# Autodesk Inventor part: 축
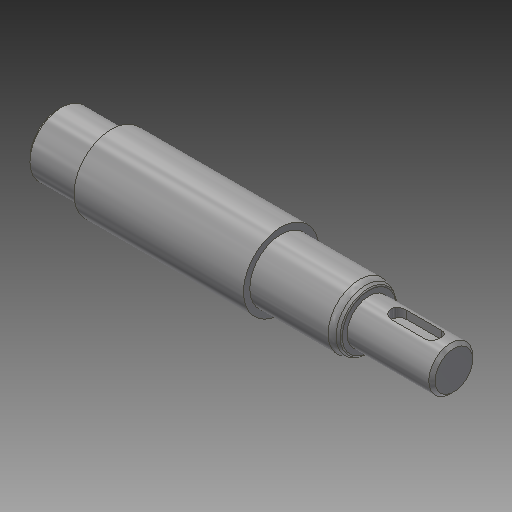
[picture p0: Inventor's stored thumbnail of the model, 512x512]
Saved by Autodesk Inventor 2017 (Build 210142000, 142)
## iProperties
Created: 2016-06
Part Number: 축
Material: 강철, 연강
Document SubType Name: Modeling
Designer: mduedu
Density: 7.86 g/cm^3
Appearance: 강철
Author: mduedu
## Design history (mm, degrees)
sketch "스케치1"
  geometry: L1 (-63, 0)-(63, 0); L2 (-63, 0)-(-63, 10); L3 (-63, 10)-(-46, 10); L4 (-46, 10)-(-46, 12); L5 (-46, 12)-(8, 12); L6 (8, 12)-(8, 10); L7 (8, 10)-(36, 10); L8 (36, 10)-(36, 7); L9 (36, 7)-(63, 7); L10 (63, 7)-(63, 0); 2 further points
  constraints: 20 end point, 5 parallel, 2 perpendicular, 1 coincident, 1 collinear, 1 horizontal, 1 midpoint, 1 vertical
  dimensions: "d0" = 126 distance of L1.start L1.end; "d2" = 14 diameter of L9 L1; "d3" = 20 diameter of L7 L1; "d4" = 24 diameter of L5 L1; "d5" = 20 diameter of L3 L1; "d6" = 17 distance of L2.end L3.end; "d7" = 27 distance of L8.end L9.end; "d8" = 55 distance from line of L5.end L10
revolve "회전1" sketch "스케치1" stored, may be unused: angle "d9" = 90 deg
sketch "스케치5"
  geometry: L1 (63, 10)-(63, -10) reference; L2 (63, -10)-(46, -10) reference; L3 (46, -10)-(46, -12) reference; L4 (46, -12)-(-8, -12) reference; L5 (-8, -12)-(-8, -10) reference; L6 (-8, -10)-(-36, -10) reference; L7 (-36, -10)-(-36, -7) reference; L8 (-36, -7)-(-63, -7) reference; L9 (-63, -7)-(-63, 7) reference; L10 (-63, 7)-(-36, 7) reference; L11 (-36, 7)-(-36, 10) reference; L12 (-36, 10)-(-8, 10) reference; L13 (-8, 10)-(-8, 12) reference; L14 (-8, 12)-(46, 12) reference; L15 (46, 12)-(46, 10) reference; L16 (46, 10)-(63, 10) reference; L17 (-63, 0)-(63, 0); L18 (-36, 8.85)-(-34.008, 10); L19 (-34.008, 10)-(-36, 10); L20 (-36, 10)-(-36, 8.85); 1 further point
  constraints: 8 end point, 2 midpoint, 2 point on line, 1 collinear, 1 perpendicular
  dimensions: "d36" = 17.7 diameter of L18.start L17; "d37" = 30 deg angle of L12 L18
revolve "회전3" sketch "스케치5" stored, may be unused: angle "d38" = 90 deg
fillet "모깎기1" dims "d13" = 4, "d39" = 0.5
node "작업 평면1"
sketch "스케치2"
  geometry: L1 (-4, 2.5)-(7, 2.5); L2 (7, -2.5)-(-4, -2.5); L3 (-4, 0)-(7, 0); L4 (-13.5, 8.561)-(-13.5, -8.561) reference; A1 r 2.5 centre (-4, 0) between (-4, 2.5) and (-4, -2.5); A2 r 2.5 centre (7, 0) between (7, -2.5) and (7, 2.5); 1 further point
  constraints: 6 end point, 4 point on circle, 3 tangent, 2 centre point, 2 parallel, 1 horizontal, 1 horizontal alignment
  dimensions: "d15" = 5 distance between parallel lines of L2 L1; "d16" = 16 dimension on A2 A1; "d40" = 7 distance edge to line of A1 L4
extrude "돌출1" cut sketch "스케치2" distance "d17" = 3; taper "d18" = 0 deg
chamfer "모따기2" distance "d19" = 1; stored, may be unused: second distance "d20" = 2, angle "d21" = 30 deg
sketch "스케치3"
  geometry: L1 (-36, -7)-(-62, -7) reference; L2 (-63, -6)-(-63, 6) reference; L3 (-39.5, -7)-(-41, -5.5); L4 (-41, -5.5)-(-41, -7); L5 (-39.5, -7)-(-41, -7); 1 further point
  constraints: 6 end point, 2 point on line, 1 collinear, 1 vertical
  dimensions: "d22" = 45 deg angle of L4 L3; "d23" = 22 distance between parallel lines of L2 L4; "d24" = 3 diameter of L3.start L4
revolve "회전2" stored, may be unused: angle "d25" = 90 deg
node "작업점1"
sketch "스케치4"
  geometry: 1 further point
hole "구멍1" sketch "스케치4" at (0, 0) diameter "d26" = 3.242; stored, may be unused: countersink angle "d30" = 90 deg, drill point angle "d32" = 120 deg; dims "d27" = 8, "d28" = 4, "d29" = 2, "d31" = 11
chamfer "모따기3" distance "d33" = 2; stored, may be unused: second distance "d34" = 2, angle "d35" = 30 deg
node "솔리드1"
node "절단 모서리 투영1"
